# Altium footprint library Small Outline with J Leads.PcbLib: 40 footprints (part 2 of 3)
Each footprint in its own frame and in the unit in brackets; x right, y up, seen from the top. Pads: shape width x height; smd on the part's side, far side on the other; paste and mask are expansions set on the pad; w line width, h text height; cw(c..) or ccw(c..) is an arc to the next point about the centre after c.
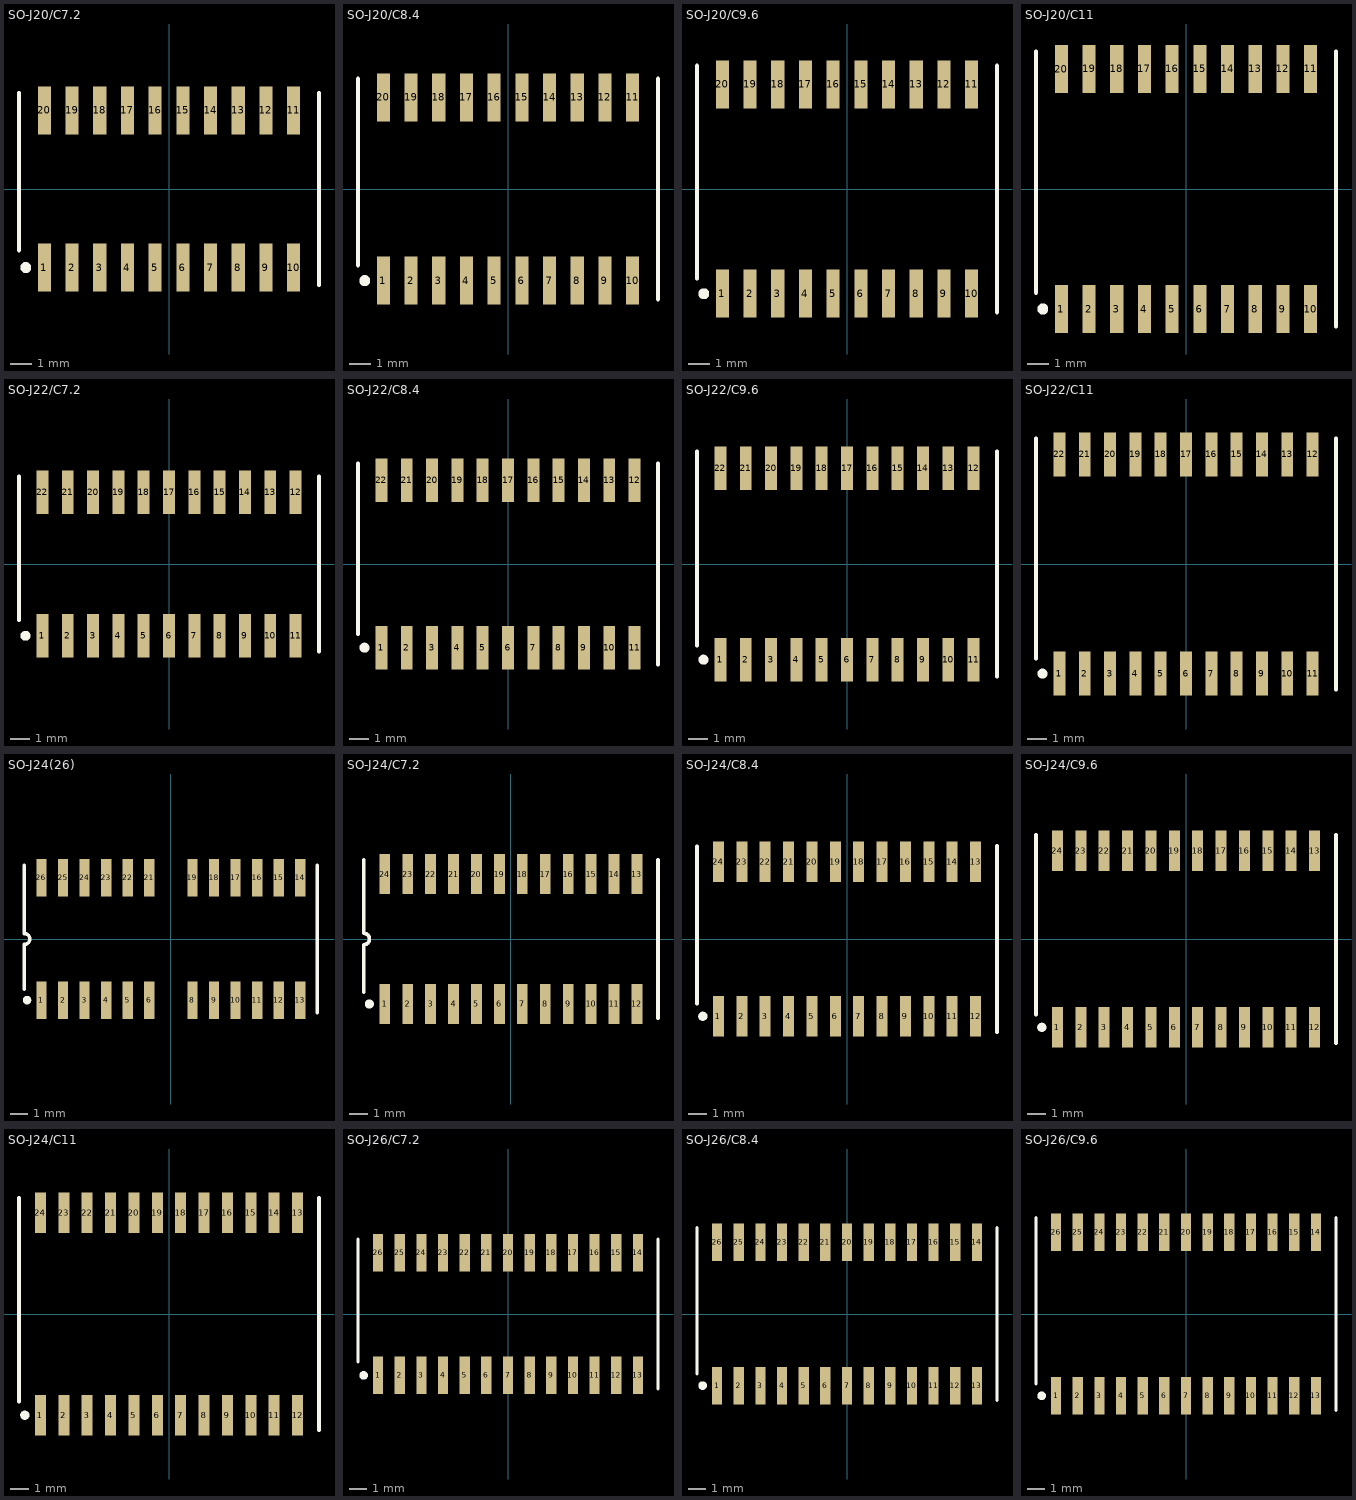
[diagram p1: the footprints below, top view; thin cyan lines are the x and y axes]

## SO-J20/C7.2 [mm]
pads (20):
  rect 0.6x2.2 smd: 1(-5.715,-3.6) 2(-4.445,-3.6) 3(-3.175,-3.6) 4(-1.905,-3.6) 5(-0.635,-3.6) 6(0.635,-3.6) 7(1.905,-3.6) 8(3.175,-3.6) 9(4.445,-3.6) 10(5.715,-3.6) 11(5.715,3.6) 12(4.445,3.6) 13(3.175,3.6) 14(1.905,3.6) 15(0.635,3.6) 16(-0.635,3.6) 17(-1.905,3.6) 18(-3.175,3.6) 19(-4.445,3.6) 20(-5.715,3.6)
Top Overlay:
  circle w0.25: c-6.565,-3.6 r0.125
  lines w0.2: -6.875,-2.8 -6.875,4.4 ; 6.875,-4.4 6.875,4.4

## SO-J20/C8.4 [mm]
pads (20):
  rect 0.6x2.2 smd: 1(-5.715,-4.2) 2(-4.445,-4.2) 3(-3.175,-4.2) 4(-1.905,-4.2) 5(-0.635,-4.2) 6(0.635,-4.2) 7(1.905,-4.2) 8(3.175,-4.2) 9(4.445,-4.2) 10(5.715,-4.2) 11(5.715,4.2) 12(4.445,4.2) 13(3.175,4.2) 14(1.905,4.2) 15(0.635,4.2) 16(-0.635,4.2) 17(-1.905,4.2) 18(-3.175,4.2) 19(-4.445,4.2) 20(-5.715,4.2)
Top Overlay:
  circle w0.25: c-6.565,-4.2 r0.125
  lines w0.2: -6.875,-3.5 -6.875,5.05 ; 6.875,-5.05 6.875,5.05

## SO-J20/C9.6 [mm]
pads (20):
  rect 0.6x2.2 smd: 1(-5.715,-4.8) 2(-4.445,-4.8) 3(-3.175,-4.8) 4(-1.905,-4.8) 5(-0.635,-4.8) 6(0.635,-4.8) 7(1.905,-4.8) 8(3.175,-4.8) 9(4.445,-4.8) 10(5.715,-4.8) 11(5.715,4.8) 12(4.445,4.8) 13(3.175,4.8) 14(1.905,4.8) 15(0.635,4.8) 16(-0.635,4.8) 17(-1.905,4.8) 18(-3.175,4.8) 19(-4.445,4.8) 20(-5.715,4.8)
Top Overlay:
  circle w0.25: c-6.565,-4.8 r0.125
  lines w0.2: -6.875,-4.1 -6.875,5.65 ; 6.875,-5.65 6.875,5.65

## SO-J20/C11 [mm]
pads (20):
  rect 0.6x2.2 smd: 1(-5.715,-5.5) 2(-4.445,-5.5) 3(-3.175,-5.5) 4(-1.905,-5.5) 5(-0.635,-5.5) 6(0.635,-5.5) 7(1.905,-5.5) 8(3.175,-5.5) 9(4.445,-5.5) 10(5.715,-5.5) 11(5.715,5.5) 12(4.445,5.5) 13(3.175,5.5) 14(1.905,5.5) 15(0.635,5.5) 16(-0.635,5.5) 17(-1.905,5.5) 18(-3.175,5.5) 19(-4.445,5.5) 20(-5.715,5.5)
Top Overlay:
  circle w0.25: c-6.565,-5.5 r0.125
  lines w0.2: -6.875,-4.75 -6.875,6.3 ; 6.875,-6.3 6.875,6.3

## SO-J22/C7.2 [mm]
pads (22):
  rect 0.6x2.2 smd: 1(-6.35,-3.6) 2(-5.08,-3.6) 3(-3.81,-3.6) 4(-2.54,-3.6) 5(-1.27,-3.6) 6(0,-3.6) 7(1.27,-3.6) 8(2.54,-3.6) 9(3.81,-3.6) 10(5.08,-3.6) 11(6.35,-3.6) 12(6.35,3.6) 13(5.08,3.6) 14(3.81,3.6) 15(2.54,3.6) 16(1.27,3.6) 17(0,3.6) 18(-1.27,3.6) 19(-2.54,3.6) 20(-3.81,3.6) 21(-5.08,3.6) 22(-6.35,3.6)
Top Overlay:
  circle w0.25: c-7.2,-3.6 r0.125
  lines w0.2: -7.525,-2.8 -7.525,4.4 ; 7.525,-4.4 7.525,4.4

## SO-J22/C8.4 [mm]
pads (22):
  rect 0.6x2.2 smd: 1(-6.35,-4.2) 2(-5.08,-4.2) 3(-3.81,-4.2) 4(-2.54,-4.2) 5(-1.27,-4.2) 6(0,-4.2) 7(1.27,-4.2) 8(2.54,-4.2) 9(3.81,-4.2) 10(5.08,-4.2) 11(6.35,-4.2) 12(6.35,4.2) 13(5.08,4.2) 14(3.81,4.2) 15(2.54,4.2) 16(1.27,4.2) 17(0,4.2) 18(-1.27,4.2) 19(-2.54,4.2) 20(-3.81,4.2) 21(-5.08,4.2) 22(-6.35,4.2)
Top Overlay:
  circle w0.25: c-7.2,-4.2 r0.125
  lines w0.2: -7.525,-3.5 -7.525,5.05 ; 7.525,-5.05 7.525,5.05

## SO-J22/C9.6 [mm]
pads (22):
  rect 0.6x2.2 smd: 1(-6.35,-4.8) 2(-5.08,-4.8) 3(-3.81,-4.8) 4(-2.54,-4.8) 5(-1.27,-4.8) 6(0,-4.8) 7(1.27,-4.8) 8(2.54,-4.8) 9(3.81,-4.8) 10(5.08,-4.8) 11(6.35,-4.8) 12(6.35,4.8) 13(5.08,4.8) 14(3.81,4.8) 15(2.54,4.8) 16(1.27,4.8) 17(0,4.8) 18(-1.27,4.8) 19(-2.54,4.8) 20(-3.81,4.8) 21(-5.08,4.8) 22(-6.35,4.8)
Top Overlay:
  circle w0.25: c-7.2,-4.8 r0.125
  lines w0.2: -7.525,-4.1 -7.525,5.65 ; 7.525,-5.65 7.525,5.65

## SO-J22/C11 [mm]
pads (22):
  rect 0.6x2.2 smd: 1(-6.35,-5.5) 2(-5.08,-5.5) 3(-3.81,-5.5) 4(-2.54,-5.5) 5(-1.27,-5.5) 6(0,-5.5) 7(1.27,-5.5) 8(2.54,-5.5) 9(3.81,-5.5) 10(5.08,-5.5) 11(6.35,-5.5) 12(6.35,5.5) 13(5.08,5.5) 14(3.81,5.5) 15(2.54,5.5) 16(1.27,5.5) 17(0,5.5) 18(-1.27,5.5) 19(-2.54,5.5) 20(-3.81,5.5) 21(-5.08,5.5) 22(-6.35,5.5)
Top Overlay:
  circle w0.25: c-7.2,-5.5 r0.125
  lines w0.2: -7.525,-4.75 -7.525,6.3 ; 7.525,-6.3 7.525,6.3

## SO-J24(26) [mm]
pads (24):
  rect 0.6x2.2 smd: 1(-7.62,-3.6) 2(-6.35,-3.6) 3(-5.08,-3.6) 4(-3.81,-3.6) 5(-2.54,-3.6) 6(-1.27,-3.6) 8(1.27,-3.6) 9(2.54,-3.6) 10(3.81,-3.6) 11(5.08,-3.6) 12(6.35,-3.6) 13(7.62,-3.6) 14(7.62,3.6) 15(6.35,3.6) 16(5.08,3.6) 17(3.81,3.6) 18(2.54,3.6) 19(1.27,3.6) 21(-1.27,3.6) 22(-2.54,3.6) 23(-3.81,3.6) 24(-5.08,3.6) 25(-6.35,3.6) 26(-7.62,3.6)
Top Overlay:
  circle w0.25: c-8.47,-3.6 r0.125
  lines w0.2: -8.625,-2.95 -8.625,-0.318 ccw(c-8.625,0) -8.625,0.318 -8.625,4.35 ; 8.625,-4.35 8.625,4.35

## SO-J24/C7.2 [mm]
pads (24):
  rect 0.6x2.2 smd: 1(-6.985,-3.6) 2(-5.715,-3.6) 3(-4.445,-3.6) 4(-3.175,-3.6) 5(-1.905,-3.6) 6(-0.635,-3.6) 7(0.635,-3.6) 8(1.905,-3.6) 9(3.175,-3.6) 10(4.445,-3.6) 11(5.715,-3.6) 12(6.985,-3.6) 13(6.985,3.6) 14(5.715,3.6) 15(4.445,3.6) 16(3.175,3.6) 17(1.905,3.6) 18(0.635,3.6) 19(-0.635,3.6) 20(-1.905,3.6) 21(-3.175,3.6) 22(-4.445,3.6) 23(-5.715,3.6) 24(-6.985,3.6)
Top Overlay:
  circle w0.25: c-7.835,-3.6 r0.125
  lines w0.2: -8.15,-2.95 -8.15,-0.318 ccw(c-8.15,0) -8.15,0.318 -8.15,4.4 ; 8.15,-4.4 8.15,4.4

## SO-J24/C8.4 [mm]
pads (24):
  rect 0.6x2.2 smd: 1(-6.985,-4.2) 2(-5.715,-4.2) 3(-4.445,-4.2) 4(-3.175,-4.2) 5(-1.905,-4.2) 6(-0.635,-4.2) 7(0.635,-4.2) 8(1.905,-4.2) 9(3.175,-4.2) 10(4.445,-4.2) 11(5.715,-4.2) 12(6.985,-4.2) 13(6.985,4.2) 14(5.715,4.2) 15(4.445,4.2) 16(3.175,4.2) 17(1.905,4.2) 18(0.635,4.2) 19(-0.635,4.2) 20(-1.905,4.2) 21(-3.175,4.2) 22(-4.445,4.2) 23(-5.715,4.2) 24(-6.985,4.2)
Top Overlay:
  circle w0.25: c-7.835,-4.2 r0.125
  lines w0.2: -8.15,-3.5 -8.15,5.044 ; 8.15,-5.05 8.15,5.05

## SO-J24/C9.6 [mm]
pads (24):
  rect 0.6x2.2 smd: 1(-6.985,-4.8) 2(-5.715,-4.8) 3(-4.445,-4.8) 4(-3.175,-4.8) 5(-1.905,-4.8) 6(-0.635,-4.8) 7(0.635,-4.8) 8(1.905,-4.8) 9(3.175,-4.8) 10(4.445,-4.8) 11(5.715,-4.8) 12(6.985,-4.8) 13(6.985,4.8) 14(5.715,4.8) 15(4.445,4.8) 16(3.175,4.8) 17(1.905,4.8) 18(0.635,4.8) 19(-0.635,4.8) 20(-1.905,4.8) 21(-3.175,4.8) 22(-4.445,4.8) 23(-5.715,4.8) 24(-6.985,4.8)
Top Overlay:
  circle w0.25: c-7.835,-4.8 r0.125
  lines w0.2: -8.15,-4.1 -8.15,5.65 ; 8.15,-5.65 8.15,5.65

## SO-J24/C11 [mm]
pads (24):
  rect 0.6x2.2 smd: 1(-6.985,-5.5) 2(-5.715,-5.5) 3(-4.445,-5.5) 4(-3.175,-5.5) 5(-1.905,-5.5) 6(-0.635,-5.5) 7(0.635,-5.5) 8(1.905,-5.5) 9(3.175,-5.5) 10(4.445,-5.5) 11(5.715,-5.5) 12(6.985,-5.5) 13(6.985,5.5) 14(5.715,5.5) 15(4.445,5.5) 16(3.175,5.5) 17(1.905,5.5) 18(0.635,5.5) 19(-0.635,5.5) 20(-1.905,5.5) 21(-3.175,5.5) 22(-4.445,5.5) 23(-5.715,5.5) 24(-6.985,5.5)
Top Overlay:
  circle w0.25: c-7.835,-5.5 r0.125
  lines w0.2: -8.15,-4.75 -8.15,6.3 ; 8.15,-6.3 8.15,6.3

## SO-J26/C7.2 [mm]
pads (26):
  rect 0.6x2.2 smd: 1(-7.62,-3.6) 2(-6.35,-3.6) 3(-5.08,-3.6) 4(-3.81,-3.6) 5(-2.54,-3.6) 6(-1.27,-3.6) 7(0,-3.6) 8(1.27,-3.6) 9(2.54,-3.6) 10(3.81,-3.6) 11(5.08,-3.6) 12(6.35,-3.6) 13(7.62,-3.6) 14(7.62,3.6) 15(6.35,3.6) 16(5.08,3.6) 17(3.81,3.6) 18(2.54,3.6) 19(1.27,3.6) 20(0,3.6) 21(-1.27,3.6) 22(-2.54,3.6) 23(-3.81,3.6) 24(-5.08,3.6) 25(-6.35,3.6) 26(-7.62,3.6)
Top Overlay:
  circle w0.25: c-8.47,-3.6 r0.125
  lines w0.2: -8.8,-2.8 -8.8,4.4 ; 8.8,-4.4 8.8,4.4

## SO-J26/C8.4 [mm]
pads (26):
  rect 0.6x2.2 smd: 1(-7.62,-4.2) 2(-6.35,-4.2) 3(-5.08,-4.2) 4(-3.81,-4.2) 5(-2.54,-4.2) 6(-1.27,-4.2) 7(0,-4.2) 8(1.27,-4.2) 9(2.54,-4.2) 10(3.81,-4.2) 11(5.08,-4.2) 12(6.35,-4.2) 13(7.62,-4.2) 14(7.62,4.2) 15(6.35,4.2) 16(5.08,4.2) 17(3.81,4.2) 18(2.54,4.2) 19(1.27,4.2) 20(0,4.2) 21(-1.27,4.2) 22(-2.54,4.2) 23(-3.81,4.2) 24(-5.08,4.2) 25(-6.35,4.2) 26(-7.62,4.2)
Top Overlay:
  circle w0.25: c-8.47,-4.2 r0.125
  lines w0.2: -8.8,-3.5 -8.8,5.05 ; 8.8,-5.05 8.8,5.05

## SO-J26/C9.6 [mm]
pads (26):
  rect 0.6x2.2 smd: 1(-7.62,-4.8) 2(-6.35,-4.8) 3(-5.08,-4.8) 4(-3.81,-4.8) 5(-2.54,-4.8) 6(-1.27,-4.8) 7(0,-4.8) 8(1.27,-4.8) 9(2.54,-4.8) 10(3.81,-4.8) 11(5.08,-4.8) 12(6.35,-4.8) 13(7.62,-4.8) 14(7.62,4.8) 15(6.35,4.8) 16(5.08,4.8) 17(3.81,4.8) 18(2.54,4.8) 19(1.27,4.8) 20(0,4.8) 21(-1.27,4.8) 22(-2.54,4.8) 23(-3.81,4.8) 24(-5.08,4.8) 25(-6.35,4.8) 26(-7.62,4.8)
Top Overlay:
  circle w0.25: c-8.47,-4.8 r0.125
  lines w0.2: -8.8,-4.1 -8.8,5.65 ; 8.8,-5.65 8.8,5.65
